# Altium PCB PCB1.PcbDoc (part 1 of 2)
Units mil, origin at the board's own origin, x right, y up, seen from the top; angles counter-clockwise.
Board outline 2505 x 2250 mil, 4 copper layers (Top Layer, GND1, GND2, Bottom Layer), stack 23.756 mil thick; 96 components, 62 nets, 306 pads, 129 vias.
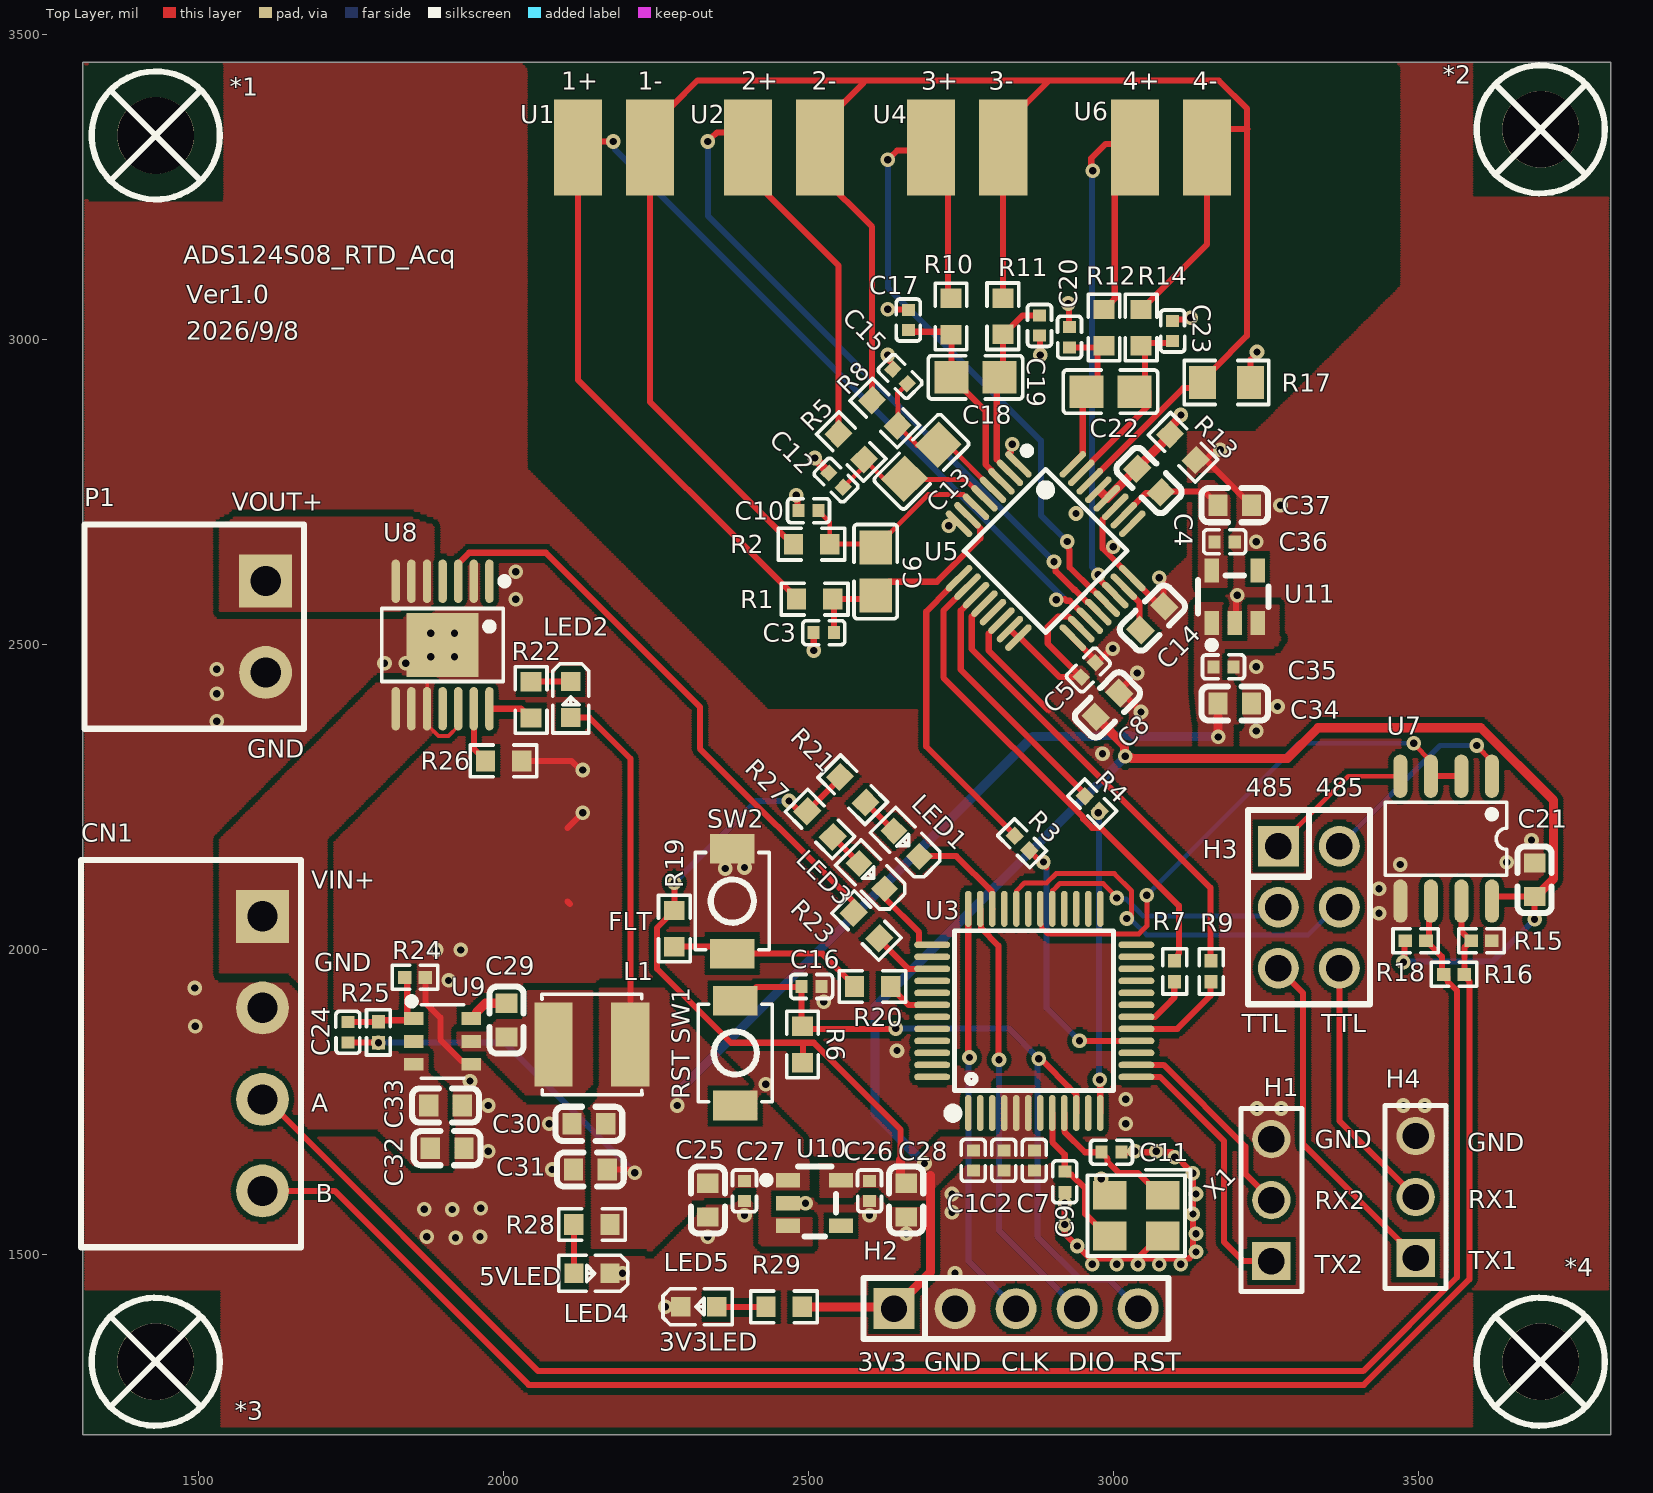
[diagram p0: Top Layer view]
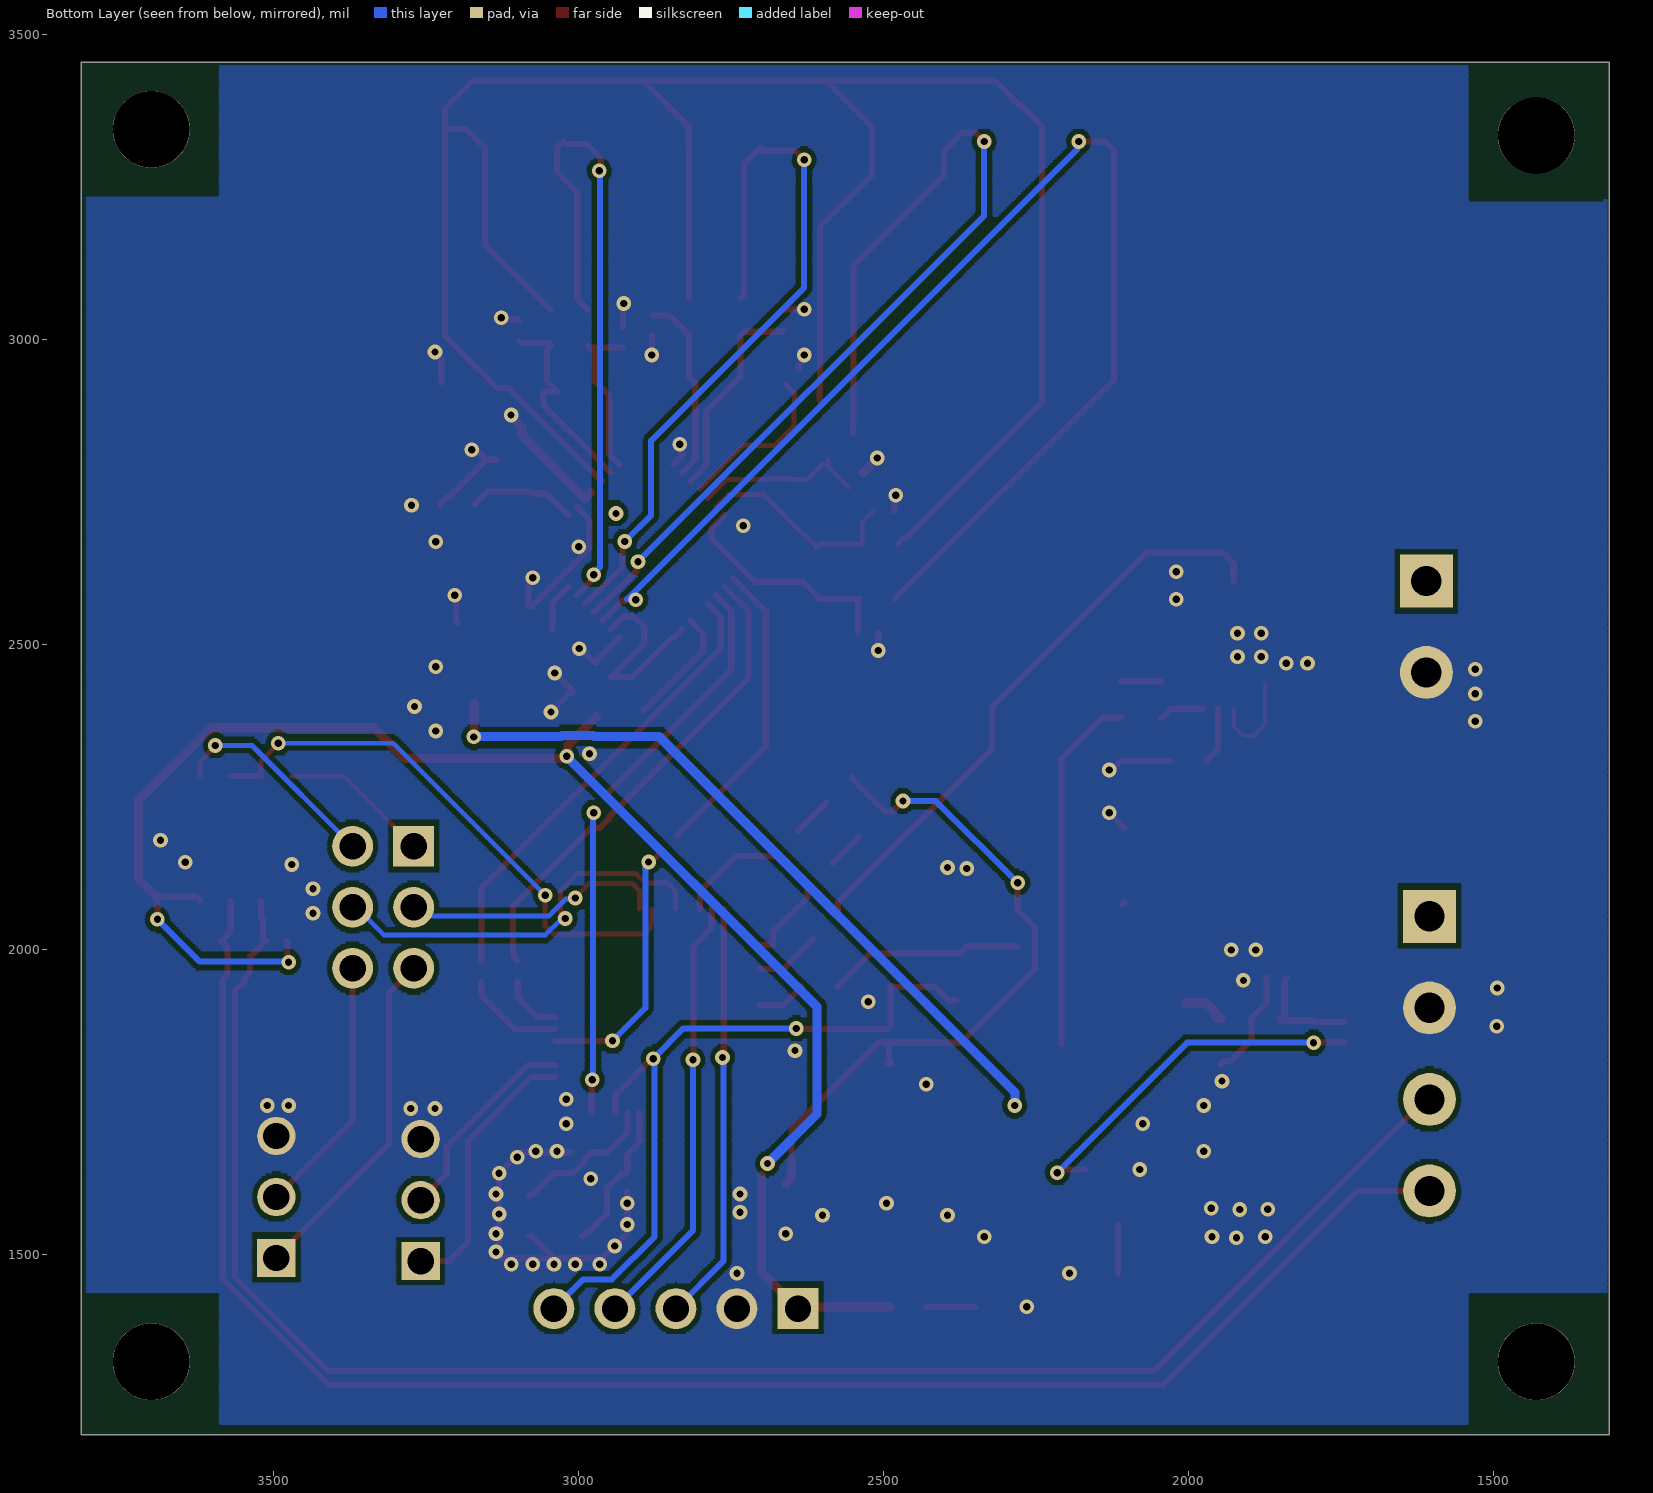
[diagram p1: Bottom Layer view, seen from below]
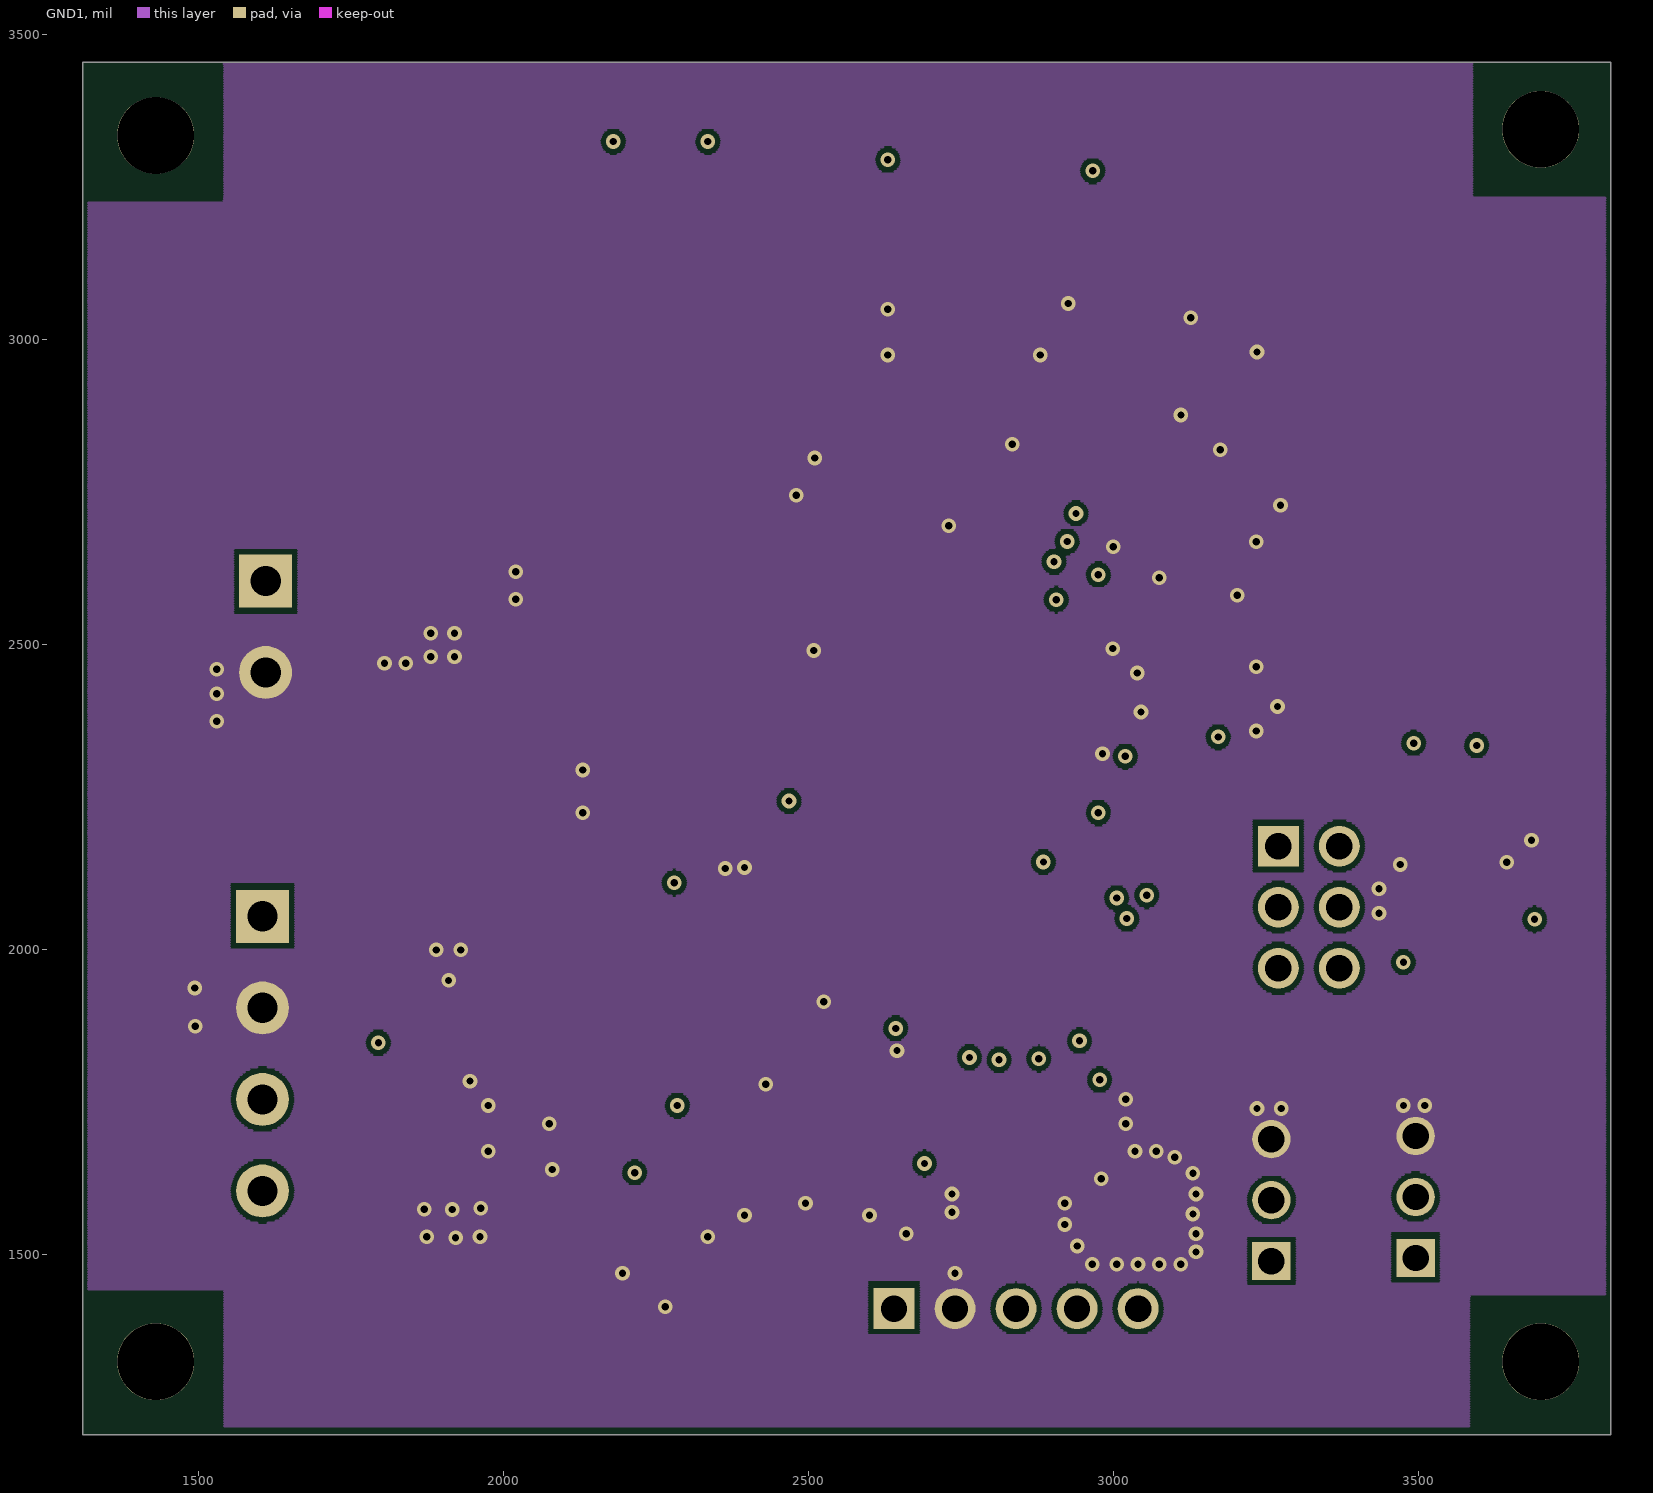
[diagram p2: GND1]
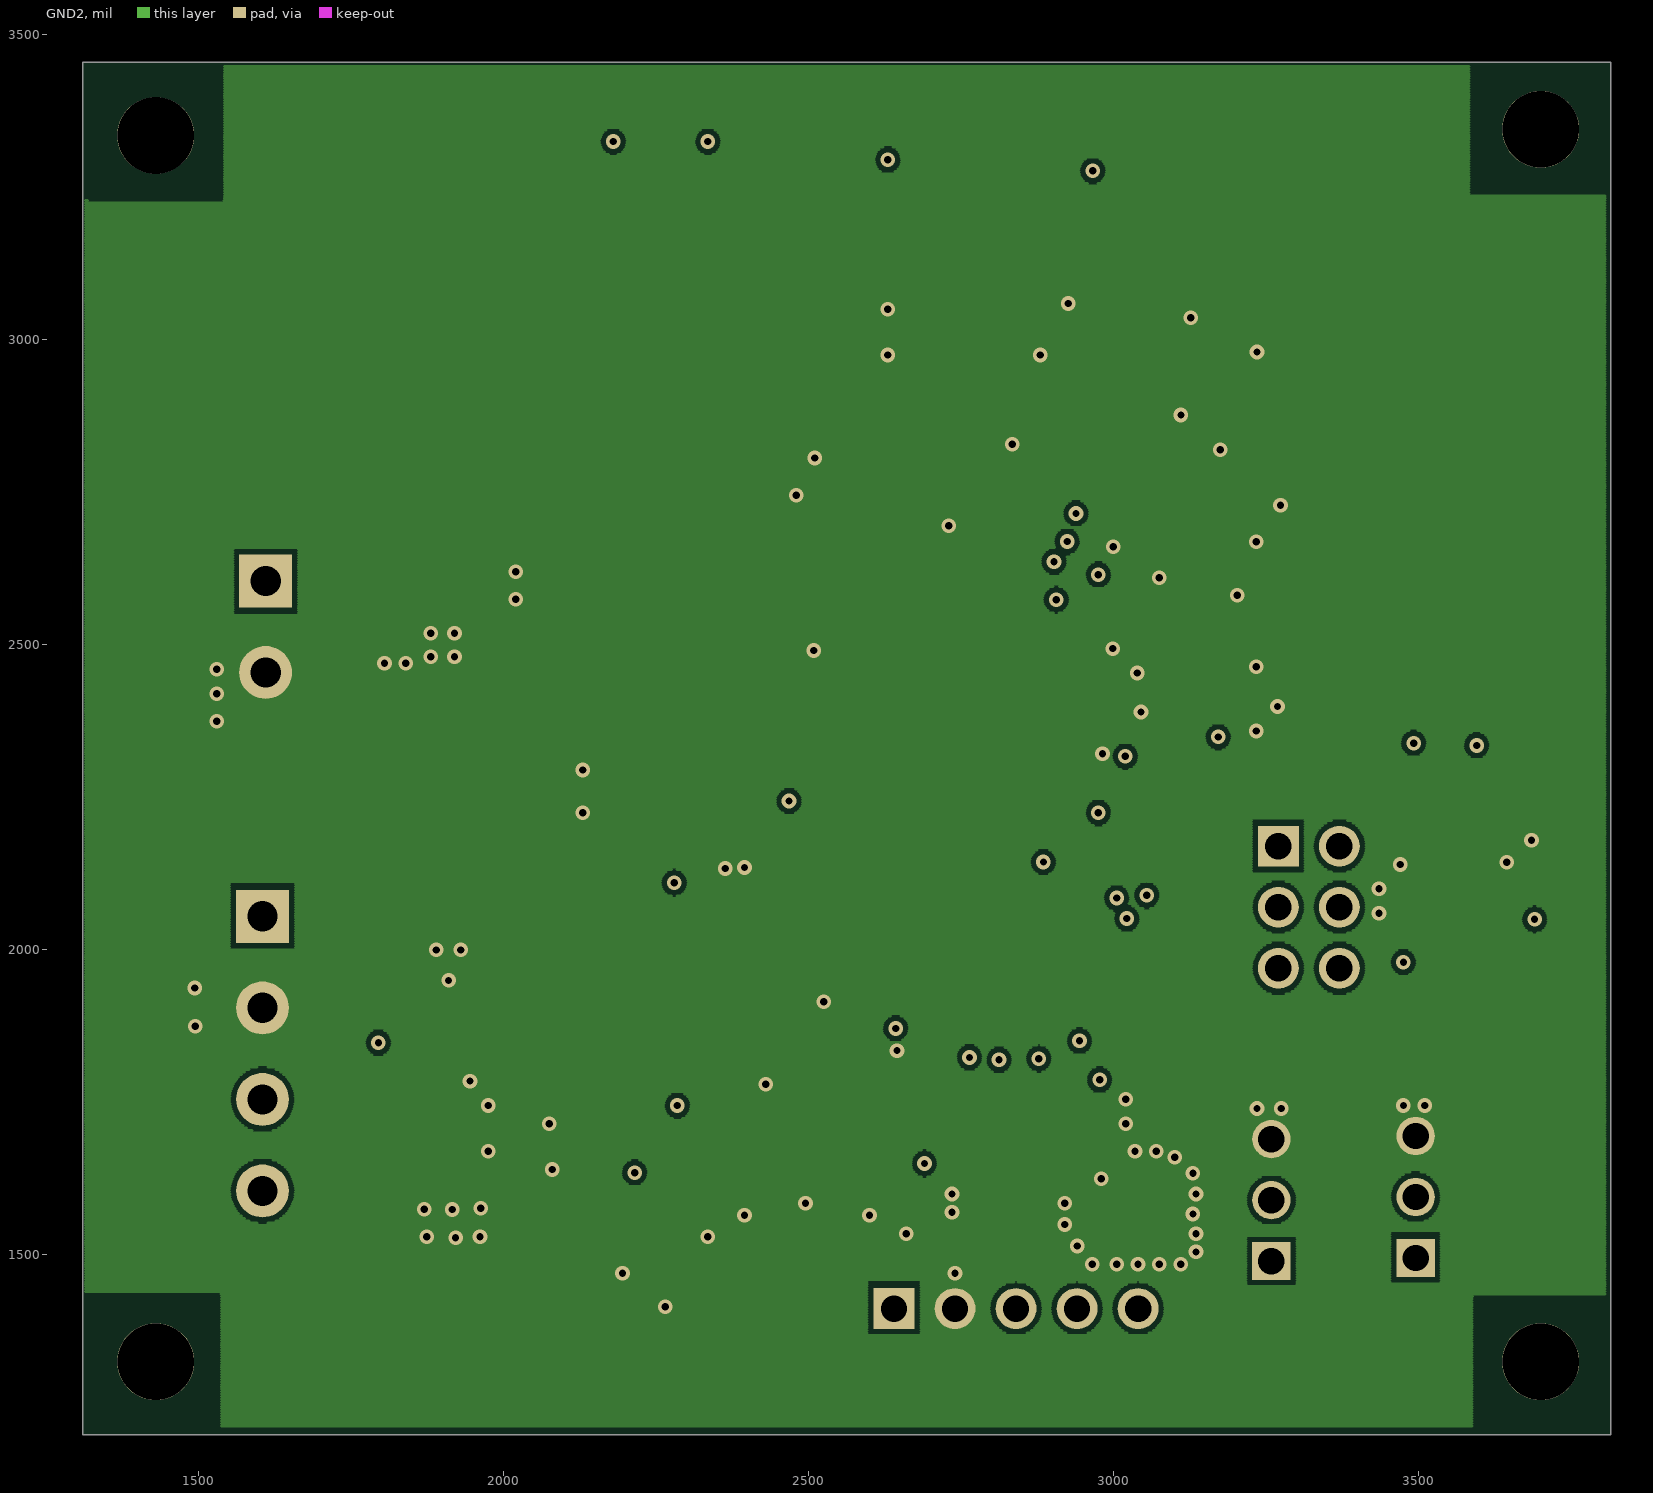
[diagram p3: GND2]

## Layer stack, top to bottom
Top Solder: solder mask 0.4, Solder Resist, Dk 3.5
Top Layer: signal copper 1.4
Dielectric 2: prepreg 2.8, PP-006, Dk 4.1
GND1: signal copper 1.378
Dielectric 1: dielectric 12.6, FR-4, Dk 4.8
GND2: signal copper 1.378
Dielectric 3: prepreg 2.8, PP-006, Dk 4.1
Bottom Layer: signal copper 1.4
Bottom Solder: solder mask 0.4, Solder Resist, Dk 3.5

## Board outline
1310,1205 1310,3455 3815,3455 3815,1205

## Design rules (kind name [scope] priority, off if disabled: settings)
Clearance [All] p1: gap=8 ignorepadtopadclearanceinfootprint=FALSE except(4: Arc-Arc Arc-Track Track-Track; 6: Arc-SMDPad Arc-THPad Arc-Via Track-SMDPad Track-THPad Track-Via SMDPad-SMDPad SMDPad-THPad SMDPad-Via THPad-THPad THPad-Via Via-Via)
ComponentClearance [All] p1: gap=0 collisioncheckmode=3 verticalgap=0 showdistances=FALSE
HoleSize [All] p1: absolutevalues=TRUE maxlimit=130 minlimit=1 maxpercent=80.000 minpercent=20.000
MinimumSolderMaskSliver [All] p1: minsoldermaskwidth=4
PlaneConnect [All] p1: planeconnectstyle=Direct reliefexpansion=20 reliefentries=4 reliefconductorwidth=10 reliefairgap=10
PolygonConnect [All] p1: connectstyle=Direct reliefconductorwidth=10 reliefentries=4 polygonreliefangle="90 Angle" airgapwidth=10
RoutingVias [All] p1: holewidth=28 width=50 viastyle="Through Hole" minholewidth=28 minwidth=50 maxholewidth=28 maxwidth=50
SilkToSilkClearance [All] p1: silktosilkclearance=2
SilkToSolderMaskClearance [IsPad] p1: minsilkscreentomaskgap=2 clearancetoexposedcopper=TRUE
SolderMaskExpansion [All] p1: expansion=0 istentingtop=FALSE
SupplyNets "Schematic Supply Nets_2" [InNet('VOUT')] p1: voltage=0.000
SupplyNets "Schematic Supply Nets_7" [InNet('GND')] p2: voltage=0.000
SupplyNets "Schematic Supply Nets_6" [InNet('VIN')] p3: voltage=0.000
SupplyNets "Schematic Supply Nets_5" [InNet('A3V3')] p4: voltage=0.000
SupplyNets "Schematic Supply Nets" [InNet('3V3')] p5: voltage=0.000
SupplyNets "Schematic Supply Nets_4" [InNet('5V')] p6: voltage=0.000
Width [All] p1: maxlimit=50 minlimit=6 preferedwidth=10
24 further rules are at their usual default settings.

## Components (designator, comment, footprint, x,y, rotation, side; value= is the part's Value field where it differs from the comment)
*1 "螺丝孔_1" M3螺丝 1430,3335 r0 top
*2 "螺丝孔_1" M3螺丝 3700,3345 r0 top
*3 "螺丝孔_1" M3螺丝 1430,1325 r0 top
*4 "螺丝孔_1" M3螺丝 3700,1325 r0 top
C1 "cc0402krx7r7bb104" C0402 2770,1655 r270 top value=100nF
C2 "cc0402krx7r7bb104" C0402 2820,1655 r270 top value=100nF
C3 "grm1555c1h472je01d" C0402 2525,2520 r180 top value=4.7nF
C4 "cl10b474ka8nnnc" C0603 3058.04,2769.4 r135 top value=470nF
C5 "cc0402krx7r7bb104" C0402 2958.55,2458.89 r225 top value=100nF
C6 "cl21b103kbannnc" C0805 2610,2620 r270 top value=10nF
C7 "cc0402krx7r7bb104" C0402 2870,1655 r270 top value=100nF
C8 "hgc0603r5106m350nthj" C0603 2989.94,2401.65 r45 top value=10uF
C9 "cc0402jrnpo9bn180" C0402 2920,1620 r270 top value=18pF
C10 "grm1555c1h472je01d" C0402 2500,2720 r180 top value=4.7nF
C11 "cc0402jrnpo9bn180" C0402 2996.46,1668.39 r180 top value=18pF
C12 "grm1555c1h472je01d" C0402 2545,2770 r135 top value=4.7nF
C13 "cl21b103kbannnc" C0805 2685,2800 r225 top value=10nF
C14 "cga0603x5r105k500jt" C0603 3063.55,2543.89 r45 top value=1uF
C15 "grm1555c1h472je01d" C0402 2650,2940 r135 top value=4.7nF
C16 "cc0402krx7r7bb104" C0402 2505,1940 r180 top value=100nF
C17 "grm1555c1h472je01d" C0402 2663.55,3032.35 r90 top value=4.7nF
C18 "cl21b103kbannnc" C0805 2773.55,2938.55 r180 top value=10nF
C19 "grm1555c1h472je01d" C0402 2878.55,3023.55 r270 top value=4.7nF
C20 "grm1555c1h472je01d" C0402 2927.77,3004.06 r90 top value=4.7nF
C21 "c1608x7r1a155kt000e" C0603 3690,2115 r270 top value=1.5uF
C22 "cl21b103kbannnc" C0805 2995,2915 r180 top value=10nF
C23 "grm1555c1h472je01d" C0402 3096.72,3014.31 r90 top value=4.7nF
C24 "cc0402jrnpo9bn101" C0402 1745,1865 r270 top value=100pF
C25 "cga0603x5r105k500jt" C0603 2335,1590 r270 top value=1uF
C26 "cc0402krx7r7bb104" C0402 2600,1605 r270 top value=100nF
C27 "cc0402krx7r7bb104" C0402 2395,1605 r270 top value=100nF
C28 "cga0603x5r105k500jt" C0603 2660,1590 r270 top value=1uF
C29 "cga0603x7r104k500jt" C0603 2005,1885 r90 top value=100nF
C30 "hgc0603r5226m160nthj" C0603 2140,1715 r0 top value=22uF
C31 "hgc0603r5226m160nthj" C0603 2142.44,1640 r0 top value=22uF
C32 "hgc0603r5106m350nthj" C0603 1907.56,1675 r180 top value=10uF
C33 "cga0603x7r104k500jt" C0603 1905,1745 r180 top value=100nF
C34 "cga0603x5r105k500jt" C0603 3198.55,2403.89 r0 top value=1uF
C35 "cc0402krx7r7bb104" C0402 3180.09,2463.89 r0 top value=100nF
C36 "cc0402krx7r7bb104" C0402 3182.01,2668.89 r0 top value=100nF
C37 "cga0603x5r105k500jt" C0603 3198.55,2728.89 r0 top value=1uF
CN1 "wj15edgrc-3.81-04p-14-00a" CONN-TH_WJ15EDGRC-3.81-4P 1605,1830 r270 top
H1 "lail-pz2.54-3p-l" HDR-TH_3P-P2.54-V-M-1 3258.69,1590 r90 top
H2 "pz254v-11-05p" HDR-TH_5P-P2.54-V-M 2840.05,1412.16 r0 top
H3 "pz254v-12-6p" HDR-TH_6P-P2.54-V-M-R2-C3-S2.54 3320,2070 r270 top
H4 "lail-pz2.54-3p-l" HDR-TH_3P-P2.54-V-M-1 3495,1595 r90 top
L1 "wpn4020h100mt" IND-SMD_L4.0-W4.0 2145,1845 r0 top value=10uH
LED1 "ltst-c190kskt" LED0603-RD 2660.85,2174.15 r135 top
LED2 "ltst-c190kskt" LED0603-RD 2110.18,2410.3 r270 top
LED3 "ltst-c190kskt" LED0603-RD 2603.89,2121.11 r135 top
LED4 "ltst-c190kskt" LED0603-RD 2145,1470 r180 top
LED5 "ltst-c190kskt" LED0603-RD 2320,1415 r0 top
P1 "wj15edgrc-3.81-02p-14-00a" CONN-TH_2P-P3.81_WJ15EDGRC-3.81-2P 1610.17,2529.78 r270 top
R1 "frc0603f1000ts" R0603 2510,2575 r180 top value=100Ω
R2 "frc0603f1000ts" R0603 2505,2665 r180 top value=100Ω
R3 "frc0402f47r0ts" R0402 2850,2175 r135 top value=47Ω
R4 "frc0402f47r0ts" R0402 2965,2240 r135 top value=47Ω
R5 "frc0603f1000ts" R0603 2570,2825 r135 top value=100Ω
R6 "frc0603f1002ts" R0603 2490,1845 r270 top value=10kΩ
R7 "frc0402f47r0ts" R0402 3100,1965 r90 top value=47Ω
R8 "frc0603f1000ts" R0603 2625,2880 r135 top value=100Ω
R9 "frc0402f47r0ts" R0402 3160,1965 r90 top value=47Ω
R10 "frc0603f1000ts" R0603 2733.55,3038.21 r90 top value=100Ω
R11 "frc0603f1000ts" R0603 2818.55,3038.55 r90 top value=100Ω
R12 "frc0603f1000ts" R0603 2984.32,3020 r90 top value=100Ω
R13 "0603waf0000t5e" R0603 3113.55,2823.89 r135 top value=0Ω
R14 "frc0603f1000ts" R0603 3045,3020 r90 top value=100Ω
R15 "0402wgf1001tce" R0402 3602.96,2015 r0 top value=1kΩ
R16 "0402wgf1200tce" R0402 3557.96,1960 r0 top value=120Ω
R17 "frc0805f3001ts" R0805 3185,2930 r0 top value=3kΩ
R18 "0402wgf1001tce" R0402 3495,2015 r0 top value=1kΩ
R19 "frc0603f4701ts" R0603 2280,2035 r90 top value=4.7kΩ
R20 "frc0603j471 ts" R0603 2605,1940 r180 top value=470Ω
R21 "0603waf1001t5e" R0603 2572.47,2262.54 r135 top value=1kΩ
R22 "0603waf1001t5e" R0603 2045.17,2409.78 r90 top value=1kΩ
R23 "0603waf1001t5e" R0603 2595,2040 r135 top value=1kΩ
R24 "rt0402brd0726k1l" R0402 1855,1955 r180 top value=26.1kΩ
R25 "frc0402f1373ts" R0402 1795,1865 r90 top value=137kΩ
R26 "frc0603f3601ts" R0603 2000.17,2309.78 r0 top value=3.6kΩ
R27 "0603waf1001t5e" R0603 2518.8,2206.2 r135 top value=1kΩ
R28 "0603waf1001t5e" R0603 2145,1550 r0 top value=1kΩ
R29 "0603waf1001t5e" R0603 2460,1415 r0 top value=1kΩ
SW1 "ts-1088-ar02016" SW-SMD_L3.9-W3.0-P4.45 2380,1831.02 r90 top
SW2 "ts-1088-ar02016" SW-SMD_L3.9-W3.0-P4.45 2375,2080 r270 top
U1 "pt1000焊盘" PT1000焊盘 2121.89,3315 r0 top
U2 "pt1000焊盘" PT1000焊盘 2400.44,3315 r0 top
U3 "stm32g031c8t6" LQFP-48_L7.0-W7.0-P0.50-LS9.0-BL 2870,1900 r0 top
U4 "pt1000焊盘" PT1000焊盘 2701.04,3315 r0 top
U5 "ads124s08ipbsr_c39676001" TQFP-32_L5.0-W5.0-P0.50-LS7.0-BL 2888.55,2653.89 r225 top
U6 "pt1000焊盘" PT1000焊盘 3035,3315 r0 top
U7 "sn65hvd75dr" SOIC-8_L4.9-W3.9-P1.27-LS6.0-BL 3545,2182.37 r180 top
U8 "tps27s100apwpr" TSSOP-14_L5.0-W4.4-P0.65-LS6.4-BL-EP 1900.17,2499.78 r180 top
U9 "ap63201wu-7" TSOT-23-6_L2.9-W1.6-P0.95-LS2.8-BR 1900,1850 r180 top
U10 "tps7a2033pdbvr" SOT-23-5_L2.9-W1.6-P0.95-LS2.8-BR 2510,1585 r180 top
U11 "tps7a2033pdbvr" SOT-23-5_L2.9-W1.6-P0.95-LS2.8-BR 3198.55,2578.89 r270 top
X1 "x32258mob4si" CRYSTAL-SMD_4P-L3.2-W2.5-BL 3037.18,1564.39 r180 top value=8MHz

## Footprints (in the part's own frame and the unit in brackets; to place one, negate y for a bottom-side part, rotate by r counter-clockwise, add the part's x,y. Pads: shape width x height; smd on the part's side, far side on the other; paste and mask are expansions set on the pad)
C0402 [mm]
  rect 0.5x0.54 smd: 1(-0.42,0) 2(0.42,0)
  silkscreen extent -0.87,-0.5 0.87,0.5
C0603 [mm]
  rect 0.8x0.9 smd: 1(-0.7,0) 2(0.7,0)
  silkscreen extent -1.39,-0.71 1.39,0.71
C0805 [mm]
  rect 1.41x1.35 smd paste-100 mask+0.051: 1(-1,0) 2(1,0)
  silkscreen extent -1.96,-0.9 1.96,0.9
CONN-TH_2P-P3.81_WJ15EDGRC-3.81-2P [mm]
  rect 2.2x2.2 hole 1.26: 1(-1.905,0)
  round 2.2 hole 1.26: 2(1.905,0)
  silkscreen extent -4.25,-7.55 4.25,1.6
CONN-TH_WJ15EDGRC-3.81-4P [mm]
  rect 2.2x2.2 hole 1.26: 1(-5.715,0)
  round 2.2 hole 1.26: 2(-1.905,0) 3(1.905,0) 4(5.715,0)
  silkscreen extent -8.06,-7.55 8.06,1.6
CRYSTAL-SMD_4P-L3.2-W2.5-BL [mm]
  rect 1.4x1.2 smd: 1(-1.1,-0.85) 2(1.1,-0.85) 3(1.1,0.85) 4(-1.1,0.85)
  silkscreen extent -2.26,-1.91 2.03,1.68
HDR-TH_3P-P2.54-V-M-1 [mm]
  rect 1.575x1.6 hole 1.1 paste-2539.97 mask+0.05: 1(-2.54,0)
  round 1.6 hole 1.1 paste-2539.97 mask+0.05: 2(0,0) 3(2.54,0)
  silkscreen extent -3.81,-1.27 3.81,1.27
HDR-TH_5P-P2.54-V-M [mm]
  rect 1.7x1.7 hole 1.1: 1(-5.08,0)
  round 1.7 hole 1.1: 2(-2.54,0) 3(0,0) 4(2.54,0) 5(5.08,0)
  silkscreen extent -6.35,-1.27 6.35,1.27
HDR-TH_6P-P2.54-V-M-R2-C3-S2.54 [mm]
  rect 1.7x1.7 hole 1.1: 1(-2.54,-1.27)
  round 1.7 hole 1.1: 2(-2.54,1.27) 3(0,-1.27) 4(0,1.27) 5(2.54,-1.27) 6(2.54,1.27)
  silkscreen extent -4.04,-2.54 4.04,2.54
IND-SMD_L4.0-W4.0 [mm]
  rect 1.6x3.5 smd: 1(-1.6,0) 2(1.6,0)
  silkscreen extent -2.08,-2.1 2.08,2.1
LED0603-RD [mm]
  rect 0.8x0.8 smd: 1(-0.749,0) 2(0.749,0)
  silkscreen extent -1.49,-0.75 1.39,0.76
LQFP-48_L7.0-W7.0-P0.50-LS9.0-BL [mm]
  oval 0.27x1.5 smd paste+0 mask+0.05: 1(-2.75,-4.25) 2(-2.25,-4.25) 3(-1.75,-4.25) 4(-1.25,-4.25) 5(-0.75,-4.25) 6(-0.25,-4.25) 7(0.25,-4.25) 8(0.75,-4.25) 9(1.25,-4.25) 10(1.75,-4.25) 11(2.25,-4.25) 12(2.75,-4.25) 25(2.75,4.25) 26(2.25,4.25) 27(1.75,4.25) 28(1.25,4.25) 29(0.75,4.25) 30(0.25,4.25) 31(-0.25,4.25) 32(-0.75,4.25) 33(-1.25,4.25) 34(-1.75,4.25) 35(-2.25,4.25) 36(-2.75,4.25)
  oval 1.5x0.27 smd paste+0 mask+0.05: 13(4.25,-2.75) 14(4.25,-2.25) 15(4.25,-1.75) 16(4.25,-1.25) 17(4.25,-0.75) 18(4.25,-0.25) 19(4.25,0.25) 20(4.25,0.75) 21(4.25,1.25) 22(4.25,1.75) 23(4.25,2.25) 24(4.25,2.75) 37(-4.25,2.75) 38(-4.25,2.25) 39(-4.25,1.75) 40(-4.25,1.25) 41(-4.25,0.75) 42(-4.25,0.25) 43(-4.25,-0.25) 44(-4.25,-0.75) 45(-4.25,-1.25) 46(-4.25,-1.75) 47(-4.25,-2.25) 48(-4.25,-2.75)
  silkscreen extent -3.59,-4.46 3.3,3.34
M3螺丝 [mil]
  round 126 hole 126 paste-99999 mask+4: 1(0,0)
  silkscreen extent -105,-105 105,105
PT1000焊盘 [mm]
  rect 2x4 smd: 1(0,0) 2(3,0)
R0402 [mm]
  rect 0.566x0.54 smd paste-100 mask+0.051: 1(-0.433,0) 2(0.433,0)
  silkscreen extent -0.94,-0.5 0.94,0.5
R0603 [mil]
  rect 31.75x34.02 smd paste-3937.01 mask+2: 1(-29.66,0) 2(29.66,0)
  silkscreen extent -55,-26 55,26
R0805 [mil]
  rect 44.59x54.21 smd paste-3937.01 mask+2: 1(-39.37,0) 2(39.37,0)
  silkscreen extent -69,-36 69,36
SOIC-8_L4.9-W3.9-P1.27-LS6.0-BL [mm]
  oval 0.588x1.8 smd paste+0 mask+0.051: 1(-1.905,-2.6) 2(-0.635,-2.6) 3(0.635,-2.6) 4(1.905,-2.6) 5(1.905,2.6) 6(0.635,2.6) 7(-0.635,2.6) 8(-1.905,2.6)
  silkscreen extent -2.53,-1.52 2.53,1.52
SOT-23-5_L2.9-W1.6-P0.95-LS2.8-BR [mm]
  rect 1x0.6 smd paste+0 mask+0.05: 1(1.1,-0.95) 2(1.1,0) 3(1.1,0.95) 4(-1.1,0.95) 5(-1.1,-0.95)
  silkscreen extent -0.89,-1.52 2.16,1.4
SW-SMD_L3.9-W3.0-P4.45 [mm]
  rect 1.23x1.86 smd: 1(-2.185,0) 2(2.185,0)
  silkscreen extent -2.03,-1.54 2.03,1.54
TQFP-32_L5.0-W5.0-P0.50-LS7.0-BL [mm]
  oval 0.28x1.45 smd: 1(-1.75,-3.35) 2(-1.25,-3.35) 3(-0.75,-3.35) 4(-0.25,-3.35) 5(0.25,-3.35) 6(0.75,-3.35) 7(1.25,-3.35) 8(1.75,-3.35) 17(1.75,3.35) 18(1.25,3.35) 19(0.75,3.35) 20(0.25,3.35) 21(-0.25,3.35) 22(-0.75,3.35) 23(-1.25,3.35) 24(-1.75,3.35)
  oval 1.45x0.28 smd: 9(3.35,-1.75) 10(3.35,-1.25) 11(3.35,-0.75) 12(3.35,-0.25) 13(3.35,0.25) 14(3.35,0.75) 15(3.35,1.25) 16(3.35,1.75) 25(-3.35,1.75) 26(-3.35,1.25) 27(-3.35,0.75) 28(-3.35,0.25) 29(-3.35,-0.25) 30(-3.35,-0.75) 31(-3.35,-1.25) 32(-3.35,-1.75)
  silkscreen extent -2.55,-3.65 2.4,2.4
TSOT-23-6_L2.9-W1.6-P0.95-LS2.8-BR [mm]
  rect 0.8x0.532 smd: 1(1.2,-0.95) 2(1.2,0) 3(1.2,0.95) 4(-1.2,0.95) 5(-1.2,0) 6(-1.2,-0.95)
  silkscreen extent -0.88,-1.82 1.44,1.53
TSSOP-14_L5.0-W4.4-P0.65-LS6.4-BL-EP [mm]
  oval 0.35x1.809 smd: 1(-1.95,-2.655) 2(-1.3,-2.655) 3(-0.65,-2.655) 4(0,-2.655) 5(0.65,-2.655) 6(1.3,-2.655) 7(1.95,-2.655) 8(1.95,2.655) 9(1.3,2.655) 10(0.65,2.655) 11(0,2.655) 12(-0.65,2.655) 13(-1.3,2.655) 14(-1.95,2.655)
  rect 3x2.65 smd: 15(0,0)
  silkscreen extent -2.73,-2.8 2.53,1.52

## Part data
C1 C2 C5 C7 C16 C26 C27 C35 C36: "容值:100nF;精度:±10%;额定电压:16V;温度系数:X7R;", JLCPCB Part Class="Extended Part", LCSC Part Name="100nF ±10% 16V", Manufacturer=YAGEO(国巨), ManufacturerPart=CC0402KRX7R7BB104, Temperature Coefficient=X7R, Tolerance=±10%, Voltage Rating=16V
C3 C10 C12 C15 C17 C19 C20 C23: "容值:4.7nF;精度:±5%;额定电压:50V;温度系数:C0G;", JLCPCB Part Class="Extended Part", LCSC Part Name="4.7nF ±5% 50V", Manufacturer=muRata(村田), ManufacturerPart=GRM1555C1H472JE01D, Temperature Coefficient=C0G, Tolerance=±5%, Voltage Rating=50V
C4: "容值:470nF;精度:±10%;额定电压:25V;温度系数:X7R;", JLCPCB Part Class="Basic Part", LCSC Part Name="470nF ±10% 25V", Manufacturer=SAMSUNG(三星), ManufacturerPart=CL10B474KA8NNNC, Temperature Coefficient=X7R, Tolerance=±10%, Voltage Rating=25V
C6 C13 C18 C22: "容值:10nF;精度:±10%;额定电压:50V;温度系数:X7R;", JLCPCB Part Class="Basic Part", LCSC Part Name="10nF ±10% 50V", Manufacturer=SAMSUNG(三星), ManufacturerPart=CL21B103KBANNNC, Temperature Coefficient=X7R, Tolerance=±10%, Voltage Rating=50V
C8 C32: "容值:10uF;精度:±20%;额定电压:35V;温度系数:X5R;", JLCPCB Part Class="Extended Part", LCSC Part Name="10uF ±20% 35V", Manufacturer=Chinocera(华瓷), ManufacturerPart=HGC0603R5106M350NTHJ, Temperature Coefficient=X5R, Tolerance=±20%, Voltage Rating=35V
C9 C11: "容值:18pF;精度:±5%;额定电压:50V;温度系数:NP0;", JLCPCB Part Class="Extended Part", LCSC Part Name="18pF ±5% 50V", Manufacturer=YAGEO(国巨), ManufacturerPart=CC0402JRNPO9BN180, Temperature Coefficient=NP0, Tolerance=±5%, Voltage Rating=50V
C14 C25 C28 C34 C37: "容值:1uF;精度:±10%;额定电压:50V;温度系数:X5R;", JLCPCB Part Class="Extended Part", LCSC Part Name="1uF ±10% 50V 停产", Manufacturer=HRE(芯声), ManufacturerPart=CGA0603X5R105K500JT, Temperature Coefficient=X5R, Tolerance=±10%, Voltage Rating=50V
C21: "容值:1.5uF;精度:±10%;额定电压:10V;温度系数:X7R;", JLCPCB Part Class="Extended Part", LCSC Part Name="1.5uF ±10% 10V", Manufacturer=TDK, ManufacturerPart=C1608X7R1A155KT000E, Temperature Coefficient=X7R, Tolerance=±10%, Voltage Rating=10V
C24: "容值:100pF;精度:±5%;额定电压:50V;温度系数:NP0;", JLCPCB Part Class="Extended Part", LCSC Part Name="100pF ±5% 50V", Manufacturer=YAGEO(国巨), ManufacturerPart=CC0402JRNPO9BN101, Temperature Coefficient=NP0, Tolerance=±5%, Voltage Rating=50V
C29 C33: "容值:100nF;精度:±10%;额定电压:50V;温度系数:X7R;", JLCPCB Part Class="Extended Part", LCSC Part Name="100nF ±10% 50V", Manufacturer=HRE(芯声), ManufacturerPart=CGA0603X7R104K500JT, Temperature Coefficient=X7R, Tolerance=±10%, Voltage Rating=50V
C30 C31: "容值:22uF;精度:±20%;额定电压:16V;温度系数:X5R;", JLCPCB Part Class="Extended Part", LCSC Part Name="22uF ±20% 16V", Manufacturer=Chinocera(华瓷), ManufacturerPart=HGC0603R5226M160NTHJ, Temperature Coefficient=X5R, Tolerance=±20%, Voltage Rating=16V
CN1: "连接器类型:板端/插座-闭口;固定方式:无固定装置;结构:1x4P;间距:3.81mm;颜色:绿色;安装方式:弯插;排数:1;每排PIN数:4;额定电流:8A;额定电压:300V;线规 - AWG:-;线规 - 平方毫米:-;工作温度:-40℃~+105℃;", Color=绿色, Current Rating=8A, JLCPCB Part Class="Extended Part", LCSC Part Name="无固定装置 1x4P 3.81mm 排数:1 每排P数:4", Manufacturer=KANGNEX(康奈克斯电气), ManufacturerPart=WJ15EDGRC-3.81-04P-14-00A, Operating Temperature=-40℃~+105℃, Voltage Rating (Max)=300V
H1 H4: "插针结构:1x3P;间距:2.54mm;圆针/方针:方针;排数:单排;总PIN位数:3P;额定电流:3A;额定电压:250V;塑高:2.5mm;端接针长度:3mm;触头材质:黄铜;触头镀层:金;工作温度:-25℃~+80℃;颜色:黑色;", Color=黑色, Current Rating=3A, JLCPCB Part Class="Extended Part", LCSC Part Name="1x3P 间距:2.54mm 方针", Manufacturer=LAILAN(莱联), ManufacturerPart=LAIL-PZ2.54-3P-L, Operating Temperature=-25℃~+80℃, Voltage Rating (Max)=250V
H2: "插针结构:1x5P;间距:2.54mm;行距:-;圆针/方针:方针;安装方式:直插;排数:单排;总PIN位数:5P;额定电流:3A;额定电压:250V;配合针长度:6mm;塑高:2.5mm;端接针长度:3mm;触头材质:黄铜;触头镀层:-;工作温度:-40℃~+105℃;颜色:黑色;", Color=黑色, Current Rating=3A, JLCPCB Part Class="Extended Part", LCSC Part Name="1x5P 间距:2.54mm 方针 直插", Manufacturer=XFCN(兴飞), ManufacturerPart=PZ254V-11-05P, Operating Temperature=-40℃~+105℃, Voltage Rating (Max)=250V
H3: "插针结构:2x3P;间距:2.54mm;行距:2.54mm;圆针/方针:方针;安装方式:直插;排数:双排;总PIN位数:6P;额定电流:3A;额定电压:-;配合针长度:6mm;塑高:2.5mm;端接针长度:3mm;触头材质:黄铜;触头镀层:金;工作温度:-40℃~+105℃;颜色:黑色;", Color=黑色, Current Rating=3A, JLCPCB Part Class="Extended Part", LCSC Part Name="2x3P 间距:2.54mm 方针 直插", Manufacturer=XFCN(兴飞), ManufacturerPart=PZ254V-12-6P, Operating Temperature=-40℃~+105℃, Voltage Rating (Max)=-
L1: "电感值:10uH;精度:±20%;额定电流:2A;饱和电流(Isat):3.5A;类型:-;", Current - Saturation(Isat)=3.5A, Current Rating=2A, DC Resistance(DCR)=216mΩ, JLCPCB Part Class="Extended Part", LCSC Part Name="10uH ±20% 3.5A", Manufacturer=Sunlord(顺络), ManufacturerPart=WPN4020H100MT, Ratings=-, Tolerance=±20%
LED1 LED2 LED3 LED4 LED5: "灯头类型:-;发光颜色:黄色;正向压降(Vf):2.1V;功率:75mW;正向电流:20mA;波长:584.5nm~597nm;二极管配置:独立二极管;透镜颜色:无色透明透镜;色温:-;发光强度:104mcd;发光角度:130°;载带方式:-;工作温度:-30℃~+85℃;", Color Temperature=-, Forward Current=20mA, Illumination Color=黄色, JLCPCB Part Class="Extended Part", LCSC Part Name=黄灯, Lens Color=无色透明透镜, Manufacturer=LITEON(光宝), ManufacturerPart=LTST-C190KSKT, Operating Temperature=-30℃~+85℃, Power(Watts)=75mW, Voltage - Forward(Vf)=2.1V
P1: "连接器类型:板端/插座-闭口;固定方式:无固定装置;结构:1x2P;间距:3.81mm;颜色:绿色;安装方式:弯插;排数:1;每排PIN数:2;额定电流:8A;额定电压:300V;线规 - AWG:-;线规 - 平方毫米:-;工作温度:-40℃~+105℃;", Color=绿色, Current Rating=8A, JLCPCB Part Class="Extended Part", LCSC Part Name="无固定装置 1x2P 3.81mm 排数:1 每排P数:2", Manufacturer=KANGNEX(康奈克斯电气), ManufacturerPart=WJ15EDGRC-3.81-02P-14-00A, Operating Temperature=-40℃~+105℃, Voltage Rating (Max)=300V
R1 R2 R5 R8 R10 R11 R12 R14: "电阻类型:厚膜电阻;阻值:100Ω;精度:±1%;功率:100mW;工作电压:75V;温度系数:±100ppm/℃;", JLCPCB Part Class="Extended Part", LCSC Part Name="100Ω ±1% 100mW 厚膜电阻", Manufacturer=FOJAN(富捷), ManufacturerPart=FRC0603F1000TS, Operating Temperature=-55℃~+155℃, Power(Watts)=100mW, Temperature Coefficient=±100ppm/℃, Tolerance=±1%, Voltage-Supply(Max)=75V
R3 R4 R7 R9: "电阻类型:厚膜电阻;阻值:47Ω;精度:±1%;功率:62.5mW;工作电压:50V;温度系数:±100ppm/℃;", JLCPCB Part Class="Extended Part", LCSC Part Name="47Ω ±1% 62.5mW 厚膜电阻", Manufacturer=FOJAN(富捷), ManufacturerPart=FRC0402F47R0TS, Operating Temperature=-55℃~+155℃, Power(Watts)=62.5mW, Temperature Coefficient=±100ppm/℃, Tolerance=±1%, Voltage-Supply(Max)=50V
R6: "电阻类型:厚膜电阻;阻值:10kΩ;精度:±1%;功率:100mW;工作电压:75V;温度系数:±100ppm/℃;", JLCPCB Part Class="Extended Part", LCSC Part Name="10kΩ ±1% 100mW 厚膜电阻", Manufacturer=FOJAN(富捷), ManufacturerPart=FRC0603F1002TS, Operating Temperature=-55℃~+155℃, Power(Watts)=100mW, Temperature Coefficient=±100ppm/℃, Tolerance=±1%, Voltage-Supply(Max)=75V
R13: "电阻类型:厚膜电阻;阻值:0Ω;精度:±1%;功率:100mW;工作电压:75V;温度系数:-;", JLCPCB Part Class="Basic Part", LCSC Part Name="0Ω ±1% 100mW 厚膜电阻", Manufacturer=UNI-ROYAL(厚声), ManufacturerPart=0603WAF0000T5E, Operating Temperature=-55℃~+155℃, Power(Watts)=100mW, Temperature Coefficient=-, Tolerance=±1%, Voltage-Supply(Max)=75V
R15 R18: "电阻类型:厚膜电阻;阻值:1kΩ;精度:±1%;功率:62.5mW;工作电压:50V;温度系数:±100ppm/℃;", JLCPCB Part Class="Basic Part", LCSC Part Name="厚膜电阻 1kΩ ±1%", Manufacturer=UNI-ROYAL(厚声), ManufacturerPart=0402WGF1001TCE, Operating Temperature=-55℃~+155℃, Power(Watts)=62.5mW, Temperature Coefficient=±100ppm/℃, Tolerance=±1%, Voltage-Supply(Max)=50V
R16: "电阻类型:厚膜电阻;阻值:120Ω;精度:±1%;功率:62.5mW;工作电压:50V;温度系数:±100ppm/℃;", JLCPCB Part Class="Basic Part", LCSC Part Name="厚膜电阻 120Ω ±1%", Manufacturer=UNI-ROYAL(厚声), ManufacturerPart=0402WGF1200TCE, Operating Temperature=-55℃~+155℃, Power(Watts)=62.5mW, Temperature Coefficient=±100ppm/℃, Tolerance=±1%, Voltage-Supply(Max)=50V
R17: "电阻类型:厚膜电阻;阻值:3kΩ;精度:±1%;功率:125mW;工作电压:150V;温度系数:±100ppm/℃;", JLCPCB Part Class="Extended Part", LCSC Part Name="3kΩ ±1% 125mW 厚膜电阻", Manufacturer=FOJAN(富捷), ManufacturerPart=FRC0805F3001TS, Operating Temperature=-55℃~+155℃, Power(Watts)=125mW, Temperature Coefficient=±100ppm/℃, Tolerance=±1%, Voltage-Supply(Max)=150V
R19: "电阻类型:厚膜电阻;阻值:4.7kΩ;精度:±1%;功率:100mW;工作电压:75V;温度系数:±100ppm/℃;", JLCPCB Part Class="Extended Part", LCSC Part Name="4.7kΩ ±1% 100mW 厚膜电阻", Manufacturer=FOJAN(富捷), ManufacturerPart=FRC0603F4701TS, Operating Temperature=-55℃~+155℃, Power(Watts)=100mW, Temperature Coefficient=±100ppm/℃, Tolerance=±1%, Voltage-Supply(Max)=75V
R20: "电阻类型:厚膜电阻;阻值:470Ω;精度:±5%;功率:100mW;工作电压:75V;温度系数:±100ppm/℃;", JLCPCB Part Class="Extended Part", LCSC Part Name="470Ω ±5% 100mW 厚膜电阻", Manufacturer=FOJAN(富捷), ManufacturerPart="FRC0603J471 TS", Operating Temperature=-55℃~+155℃, Power(Watts)=100mW, Temperature Coefficient=±100ppm/℃, Tolerance=±5%, Voltage-Supply(Max)=75V
R21 R22 R23 R27 R28 R29: "电阻类型:厚膜电阻;阻值:1kΩ;精度:±1%;功率:100mW;工作电压:75V;温度系数:±100ppm/℃;", JLCPCB Part Class="Basic Part", LCSC Part Name="1kΩ ±1% 100mW 厚膜电阻", Manufacturer=UNI-ROYAL(厚声), ManufacturerPart=0603WAF1001T5E, Operating Temperature=-55℃~+155℃, Power(Watts)=100mW, Temperature Coefficient=±100ppm/℃, Tolerance=±1%, Voltage-Supply(Max)=75V
R24: "电阻类型:薄膜电阻;阻值:26.1kΩ;精度:±0.1%;功率:62.5mW;工作电压:50V;温度系数:±25ppm/℃;", JLCPCB Part Class="Extended Part", LCSC Part Name="薄膜电阻 26.1kΩ ±0.1% 62.5mW", Manufacturer=YAGEO(国巨), ManufacturerPart=RT0402BRD0726K1L, Operating Temperature=-55℃~+155℃, Power(Watts)=62.5mW, Temperature Coefficient=±25ppm/℃, Tolerance=±0.1%, Voltage-Supply(Max)=50V
R25: "电阻类型:厚膜电阻;阻值:137kΩ;精度:±1%;功率:62.5mW;工作电压:50V;温度系数:±100ppm/℃;", JLCPCB Part Class="Extended Part", LCSC Part Name="137kΩ ±1% 62.5mW 厚膜电阻", Manufacturer=FOJAN(富捷), ManufacturerPart=FRC0402F1373TS, Operating Temperature=-55℃~+155℃, Power(Watts)=62.5mW, Temperature Coefficient=±100ppm/℃, Tolerance=±1%, Voltage-Supply(Max)=50V
R26: "电阻类型:厚膜电阻;阻值:3.6kΩ;精度:±1%;功率:100mW;工作电压:75V;温度系数:±100ppm/℃;", JLCPCB Part Class="Extended Part", LCSC Part Name="3.6kΩ ±1% 100mW 厚膜电阻", Manufacturer=FOJAN(富捷), ManufacturerPart=FRC0603F3601TS, Operating Temperature=-55℃~+155℃, Power(Watts)=100mW, Temperature Coefficient=±100ppm/℃, Tolerance=±1%, Voltage-Supply(Max)=75V
SW1 SW2: "电路结构:单刀单掷;按钮形状:圆形按钮;作用力:1.6N;安装方式:立贴;开关长度:3.9mm;开关宽度:3mm;开关高度:2mm;带支架:不带支架;触点电流:50mA;额定电压:12V;带灯:-;工作寿命:10万次;", Actuator/Cap Color=黑色, Contact Current=50mA, IP Rating=-, JLCPCB Part Class="Basic Part", LCSC Part Name="3.9*3*2mm 立贴 轻触开关", Manufacturer=XUNPU(讯普), ManufacturerPart=TS-1088-AR02016, Operating Force=1.6N, Operating Temperature=-30℃~+80℃, Voltage Rating=12V
U3: "CPU内核:ARM Cortex-M0+;CPU最大主频:64MHz;CPU位数:32 Bit;", JLCPCB Part Class="Extended Part", LCSC Part Name="主流Arm Cortex-M0+ MCU，具有64 KB Flash存储器、8 KB RAM、64 MHz CPU、2x USART、定时器、ADC和通信接口，1.7-3.6V", Manufacturer=ST(意法半导体), ManufacturerPart=STM32G031C8T6, Operating Temperature=-40℃~+85℃, Voltage - Supply=1.7V~3.6V
U5: "分辨率(位):24;采样率:4kHz;工作电压:2.7V~5.25V;接口类型:SPI;", Clock Frequency=4.096MHz, JLCPCB Part Class="Extended Part", LCSC Part Name="具有PGA和电压基准的低功耗、低噪声、高集成度6通道及12通道4kSPS、24位∑-Δ ADC", Manufacturer=TI(德州仪器), ManufacturerPart=ADS124S08IPBSR, Operating Temperature=-50℃~+125℃, Quiescent Current (Iq)=280uA, Voltage - Supply=2.7V~5.25V, Voltage Reference=内置
U7: "类型:收发器;数据速率:20Mbps;", JLCPCB Part Class="Extended Part", LCSC Part Name="SN65HVD72, SN65HVD75, SN65HVD78 具有IEC ESD保护的3.3V电源RS-485", Manufacturer=TI(德州仪器), ManufacturerPart=SN65HVD75DR, Operating Temperature=-40℃~+125℃, Quiescent Supply Current=950uA, Voltage - Supply=3V~3.6V
U8: "类型:高侧开关;通道数:1;输入控制逻辑:高电平有效;工作电压:3.5V~40V;最大连续电流:4A;导通电阻:80mΩ;", JLCPCB Part Class="Extended Part", LCSC Part Name=单通道高侧开关，具备全面诊断功能、宽工作电压范围和可调节电流限制, Manufacturer=TI(德州仪器), ManufacturerPart=TPS27S100APWPR, Maximum Continuous Current=4A, Operating Temperature	-=-40℃~+125℃, Voltage - Supply=3.5V~40V
U9: "功能类型:降压型;工作电压:3.8V~32V;输出电压:-;输出电流:2A;输出类型:可调;", Frequency - Switching=500kHz, JLCPCB Part Class="Extended Part", LCSC Part Name="降压型 2A 3.8V~32V", Manufacturer=DIODES(美台), ManufacturerPart=AP63201WU-7, Operating Temperature=-40℃~+85℃, Output Current=2A, Output Voltage=-, Quiescent Current=22uA, Voltage - Supply=3.8V~32V
U10 U11: "输出类型:固定;最大输入电压:6V;输出电压:3.3V;输出电流:300mA;输出极性:正极;", Dropout Voltage=140mV@(300mA), JLCPCB Part Class="Extended Part", LCSC Part Name="具有高 PSRR 的 300mA、超低噪声、低 IQ、低压降 (LDO) 线性稳压器", Manufacturer=TI(德州仪器), ManufacturerPart=TPS7A2033PDBVR, Maximum Input Voltage=6V, Operating Temperature=-40℃~+125℃@(Tj), Output Current=300mA, Output Voltage=3.3V, standby current=15uA
X1: "晶振类型:贴片晶振;频率:8MHz;常温频差:±10ppm;负载电容:12pF;频率稳定度:±20ppm;", Equivalent Series Resistance(ESR)=180Ω, Frequency Stability=±20ppm, JLCPCB Part Class="Extended Part", LCSC Part Name="YSX321SL 8MHZ 4P 3225 12PF ±10PPM -40~85℃ (±20PPM)", Load Capacitance=12pF, Manufacturer=YXC(扬兴晶振), ManufacturerPart=X32258MOB4SI, Normal temperature Frequency Tolerance=±10ppm, Operating Temperature=-40℃~+85℃

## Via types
v1: diameter 24, hole 12, Top Layer to Bottom Layer, tented both sides, 125 vias
v2: diameter 24, hole 12, Top Layer to Bottom Layer, 4 vias

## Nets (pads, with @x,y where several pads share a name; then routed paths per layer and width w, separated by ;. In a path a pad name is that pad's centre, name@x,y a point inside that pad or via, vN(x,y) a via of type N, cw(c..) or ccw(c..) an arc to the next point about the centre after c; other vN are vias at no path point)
3V3: C1.1 C2.1 C5.2 C7.1 C8.1 C21.2 C26.1 C28.1 H2.1 R6.2 R18.1 R19.2 R21.2 R27.2 R29.2 U3.4 U3.5 U3.6 U5.15 U5.16 U5.18 U7.8 U10.5 | length 4159
  Top Layer w10: v1(2280,2110) R19.2@2280,2064.66 2251.58,2036.24 2251.58,1969.08 2372.87,1847.78 2491.13,1847.78 ; v1(2467.99,2244.01) 2484.82,2227.18 R27.2@2497.82,2227.18 2551.49,2280.84 R21.2@2551.49,2283.51 ; R6.2@2491.13,1815.34 2491.13,1847.78 ; 2650.66,1655.81 2650.66,1705.94 2508.82,1847.78 2491.13,1847.78 ; U5.15@2830.1,2525.82 U5.16@2844.01,2511.91 2844.68,2511.91 2845.69,2512.91 2911.41,2447.19 C5.2@2946.86,2447.19 2892.09,2501.96 2892.09,2529.66 2909.14,2546.7 2925.87,2546.7 2946.74,2525.83 U5.18@2947.02,2525.83 ; v1(3475,1980) 3476.48,1981.48 3476.48,2013.52 R18.1@3477.96,2015 ; U7.8@3620,2080 3620,2081.37 3626.07,2087.44 C21.2@3690,2087.44 v1(3690,2050)
  Top Layer w15: R29.2@2489.66,1415 2637.2,1415 H2.1@2640.05,1412.16 2700,1472.11 2700,1630 ; R6.2@2490,1815.34 R6.2@2491.13,1815.34 ; 2650.66,1655.81 2650.66,1625.81 2658.91,1617.56 C28.1@2660,1617.56 ; C8.1@2970.46,2382.16 3017.79,2334.83 3017.79,2318.88 3020.94,2315.74 3027.3,2315.74 3029.02,2314.02 3284.93,2314.02 3335.13,2364.21 3601.85,2364.21 3721.22,2244.85 3721.22,2116.69 3691.97,2087.44 C21.2@3690,2087.44
  Bottom Layer w10: v1(2280,2110) 2414.01,2244.01 v1(2467.99,2244.01) ; v1(3475,1980) 3476.19,1981.19 3621.19,1981.19 v1(3690,2050)
  Bottom Layer w15: v1(2690,1650) 2609.18,1730.82 2609.18,1907.21 v1@3019.61,2317.64
  other v1: 3019.21,2317.46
